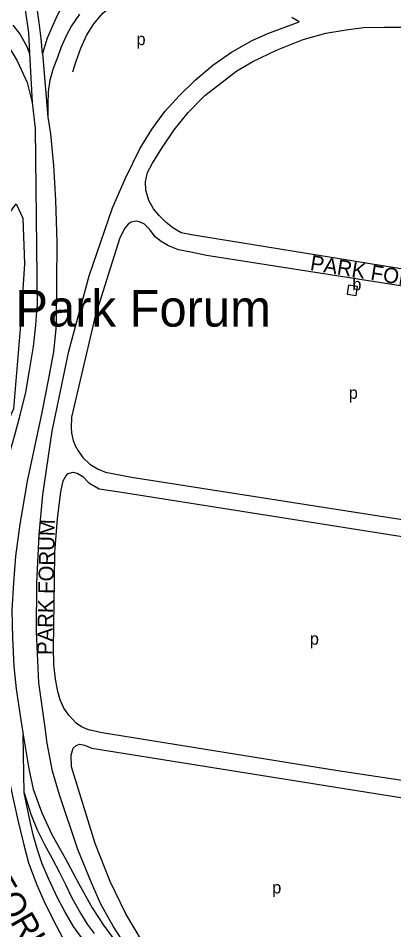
# Model space of a CAD drawing. Extents: x 154320 to 156262, y 382651 to 384180.
# Drawn here: x 155184.2 to 155307.4, y 383173 to 383472.2 of the extents above; entities that cross this region are included whole.
import ezdxf

# ---------------------------------------------------------------- set-up
doc = ezdxf.new("R2010")
doc.units = 0
for name, color, linetype in [('BLT_Basislijn', 7, 'Continuous'), ('BLT_Bebouwing', 7, 'Continuous'), ('BLT_Centroide', 7, 'Continuous'), ('BLT_Sport_parknaam', 7, 'Continuous'), ('BLT_Straatnaam', 7, 'Continuous'), ('BLT_Straatnaam_hoofdweg', 7, 'Continuous'), ('BLT_Vlakafsluiter', 7, 'Continuous')]:
    doc.layers.add(name, color=color, linetype=linetype)

msp = doc.modelspace()

# ---------------------------------------------------------------- linework, layer by layer
at = {"layer": 'BLT_Basislijn'}
msp.add_line((155217.4, 383316.76), (155341.44, 383297.14), dxfattribs=at)
for points in [[(155180.25, 383504.95), (155183.56, 383490.78), (155186.39, 383475.66), (155187.57, 383467.39), (155187.93, 383460.65)], [(155192.18, 383460.54), (155191.71, 383465.5), (155191.11, 383470.81), (155190.17, 383476.84), (155189.58, 383482.15), (155189.23, 383486.17), (155188.4, 383491.25), (155187.57, 383495.15), (155186.51, 383500.23), (155184.97, 383505.66)], [(155218.87, 383501.76), (155218.04, 383499.87), (155216.86, 383498.22), (155215.56, 383496.68), (155214.02, 383495.03), (155212.37, 383493.49), (155210.36, 383491.72), (155208.59, 383489.83), (155206.82, 383488.06), (155205.17, 383486.05), (155203.51, 383484.04), (155201.98, 383481.8), (155200.44, 383479.08), (155199.03, 383476.84), (155197.02, 383473.06), (155195.25, 383469.16), (155193.71, 383465.61), (155192.18, 383460.54)], [(155138.51, 383485.81), (155145.83, 383485.34), (155153.39, 383483.69), (155159.29, 383481.56), (155164.72, 383478.49), (155170.15, 383474.71), (155174.17, 383471.4), (155180.07, 383464.55), (155183.85, 383458.17), (155187.16, 383451.08), (155188.81, 383444.47)], [(155202.12, 383454.55), (155203.22, 383458.05), (155204.71, 383462.35), (155206.67, 383466.46), (155209.07, 383470.32), (155212, 383473.81), (155215.49, 383476.72), (155219.45, 383478.96), (155223.73, 383480.5), (155228.19, 383481.44), (155232.72, 383481.87), (155237.27, 383481.91), (155241.78, 383481.33), (155246.23, 383480.38), (155253.43, 383478.2), (155258.13, 383477.52)], [(155220.19, 383166.79), (155215.35, 383174.23), (155211.34, 383181.44), (155208.27, 383188.41), (155203.78, 383199.39), (155197.76, 383217.35), (155195.51, 383225.03), (155193.74, 383234.24), (155193.03, 383239.44), (155191.02, 383254.09), (155190.2, 383270.87), (155190.32, 383286.82), (155191.14, 383302.65), (155192.32, 383315.76), (155195.39, 383336.67), (155200.83, 383362.9), (155207.44, 383387.59), (155215.11, 383409.91), (155219.37, 383419.72), (155224.09, 383429.29), (155227.99, 383435.55), (155232.36, 383441.57), (155236.96, 383446.65), (155242.28, 383451.85), (155248.06, 383456.81), (155254.2, 383461.07), (155260.93, 383464.85), (155266.13, 383467.21), (155276.4, 383470.99)], [(155204.37, 383473.47), (155201.65, 383469.69), (155200, 383466.38), (155198.23, 383462.48), (155197.05, 383459.29), (155195.63, 383455.63), (155194.57, 383451.85), (155194.09, 383448.07), (155193.98, 383444.05), (155193.98, 383439.68)], [(155276.4, 383470.99), (155273.92, 383472.41)], [(155187.93, 383460.65), (155187.1, 383462.78), (155186.04, 383464.79), (155184.62, 383467.27), (155182.61, 383469.87)], [(155323.99, 383387.63), (155241.03, 383401.05), (155237.69, 383401.77), (155234.94, 383403.37), (155232.76, 383405.11), (155230.44, 383407.43), (155228.55, 383409.61), (155227.1, 383412.37), (155226.08, 383415.71), (155225.94, 383418.47), (155226.67, 383421.51), (155228.26, 383424.56), (155231.31, 383429.5), (155235.37, 383435.59), (155240.01, 383441.25), (155245.38, 383446.77), (155252.06, 383451.99), (155255.97, 383454.9), (155261.2, 383457.95), (155268.89, 383461.72), (155277.74, 383465.2), (155285.14, 383467.24), (155291.81, 383468.4), (155297.47, 383469.12), (155304.29, 383469.27), (155311.69, 383469.27)], [(155188.81, 383444.47), (155189.76, 383435.96), (155190.46, 383377.6)], [(155193.98, 383439.68), (155194.8, 383434.25), (155195.75, 383423.85), (155196.46, 383412.51), (155196.93, 383398.69), (155196.81, 383385.34), (155196.69, 383371.28), (155195.75, 383362.66), (155194.09, 383353.44), (155191.97, 383342.81), (155187.13, 383320.25), (155184.77, 383306.19), (155183.35, 383295.68), (155182.64, 383286.93), (155182.17, 383277.95), (155182.29, 383268.86), (155182.76, 383259.41), (155183.59, 383252.08), (155184.77, 383244.05), (155185.83, 383236.96)], [(155355.71, 383377.14), (155245.96, 383394.26), (155240.8, 383395.39), (155236.76, 383396.2), (155233.54, 383397.49), (155231.12, 383398.94), (155229.18, 383400.39), (155227.24, 383402.98), (155225.63, 383404.59), (155224.01, 383405.4), (155222.88, 383405.56), (155221.27, 383405.24), (155220.3, 383404.59), (155219.17, 383403.3), (155217.56, 383400.07), (155209.49, 383374.4), (155201.74, 383341.3), (155201.58, 383337.91), (155201.74, 383335.97), (155202.23, 383333.55), (155202.87, 383331.94), (155203.84, 383330.16), (155205.45, 383328.06), (155207.71, 383325.8), (155210.46, 383324.19), (155212.88, 383323.22), (155221.43, 383321.6), (155362.65, 383299.48)], [(155184.9, 383341.94), (155186.68, 383349.48), (155187.93, 383356.55), (155189.18, 383364.41), (155190.03, 383371.43), (155190.46, 383377.6)], [(155132.91, 383250.38), (155139.25, 383256.56), (155144.36, 383261.52), (155147.25, 383264.79), (155150.32, 383268.55), (155154.4, 383274.12), (155157.15, 383278.41), (155159.45, 383282.09), (155163.82, 383290.01), (155167.01, 383295.76), (155169.14, 383300.27), (155173.52, 383308.98), (155176.51, 383315.32), (155178.87, 383321.66), (155180.87, 383327.77), (155182.98, 383334.97), (155184.9, 383341.94)], [(155326.09, 383219.62), (155289.06, 383225.21), (155211.75, 383237.65), (155207.23, 383238.61), (155204.97, 383239.58), (155203.19, 383240.88), (155200.77, 383243.46), (155199.16, 383245.72), (155198.03, 383248.46), (155197.22, 383251.21), (155196.42, 383255.24), (155195.93, 383260.09), (155195.77, 383265.42), (155196.08, 383287.52), (155196.25, 383296.9), (155197.06, 383307.88), (155198.19, 383316.76), (155199, 383320.31), (155199.81, 383321.93), (155200.61, 383322.73), (155202.23, 383323.22), (155203.52, 383322.89), (155205.45, 383321.76), (155207.39, 383319.67), (155210.78, 383317.73), (155217.4, 383316.76)], [(155185.83, 383236.96), (155187.72, 383225.86), (155189.14, 383219.12), (155191.97, 383211.44), (155195.39, 383204.12), (155199.65, 383196.56), (155204.01, 383188.29), (155208.5, 383180.26), (155212.16, 383174.59), (155216.41, 383168.8)], [(155179.8, 383233.1), (155181.73, 383219.99), (155184.12, 383208.96), (155186.05, 383200.91), (155187.54, 383194.95), (155190.37, 383187.8), (155192.61, 383182.58), (155195.58, 383176.47), (155199.01, 383170.07), (155202.73, 383163.66), (155206.61, 383158.74), (155211.97, 383152.18), (155217.63, 383146.37), (155223.74, 383141.16), (155229.25, 383137.28), (155236.55, 383132.66), (155242.95, 383129.23), (155248.17, 383127.3), (155255.17, 383125.06), (155263.36, 383121.93), (155269.62, 383120)], [(155224.98, 383169.03), (155219.5, 383178.23), (155214.33, 383188.89), (155209.49, 383201.32), (155201.74, 383226.51), (155201.58, 383230.38), (155202.23, 383232.64), (155203.19, 383233.45), (155204.32, 383233.93), (155205.94, 383233.61), (155208.36, 383232.64), (155314.48, 383215.66)], [(155205.81, 383169.24), (155202.31, 383174.16), (155199.48, 383179.08), (155197.17, 383183.33), (155194.12, 383189.88), (155192.11, 383194.65), (155190.54, 383199.27), (155189.13, 383204.19), (155188.09, 383208.51), (155186.15, 383217.97)], [(155186.15, 383217.97), (155188.38, 383210.97), (155190.47, 383205.83), (155192.85, 383200.99), (155195.31, 383196.37), (155197.77, 383191.82), (155199.78, 383187.87), (155201.79, 383183.55), (155204.62, 383178.48), (155206.86, 383174.91), (155209.09, 383171.85)]]:
    msp.add_lwpolyline(points, dxfattribs=at)
msp.add_lwpolyline([(155183.57, 383411.21), (155185.73, 383406.58), (155186.25, 383391.6), (155184.96, 383371.6), (155182.67, 383343.96), (155176.02, 383329.21), (155171.58, 383323.23), (155171.38, 383312.11), (155165.03, 383306.92), (155155.47, 383301.87), (155148.33, 383303.32), (155140.34, 383308.02), (155136.11, 383305.37), (155132.63, 383307.36), (155134.7, 383318.27), (155143.66, 383339.38), (155151.14, 383349.48), (155155.97, 383353.05), (155162.08, 383354.62), (155165.05, 383365.81), (155167.31, 383380.95), (155169.91, 383388.52), (155179.96, 383406.31)], close=True, dxfattribs=at)
at = {"layer": 'BLT_Bebouwing'}
msp.add_lwpolyline([(155292.57, 383384.57), (155292.11, 383381.64), (155295.05, 383381.18), (155295.51, 383384.11)], close=True, dxfattribs=at)
at = {"layer": 'BLT_Vlakafsluiter'}
for p, q in [((155187.93, 383460.65), (155188.81, 383444.47)), ((155192.18, 383460.54), (155193.98, 383439.68)), ((155186.15, 383217.97), (155185.83, 383236.96))]:
    msp.add_line(p, q, dxfattribs=at)

# ---------------------------------------------------------------- texts
at = {"layer": 'BLT_Centroide'}
for s, p in [('p', (155223.02, 383463.34)), ('b', (155293.81, 383382.88)), ('p', (155292.65, 383347.26)), ('p', (155279.88, 383266.57)), ('p', (155267.54, 383184.94))]:
    msp.add_text(s, height=4, dxfattribs=at).set_placement(p)
at = {"layer": 'BLT_Sport_parknaam'}
msp.add_text('Bedrijventerrein Park Forum', height=12, dxfattribs=at).set_placement((155066.45, 383370.98))
at = {"layer": 'BLT_Straatnaam'}
for rotation, p in [(350.8268, (155279.75, 383389.55)), (88.8268, (155195.37, 383263.15))]:
    msp.add_text('PARK FORUM', height=5, rotation=rotation, dxfattribs=at).set_placement(p)
at = {"layer": 'BLT_Straatnaam_hoofdweg'}
msp.add_text('PARK FORUM', height=8, rotation=300, dxfattribs=at).set_placement((155157.95, 383216.39))

doc.saveas('drawing.dxf')
